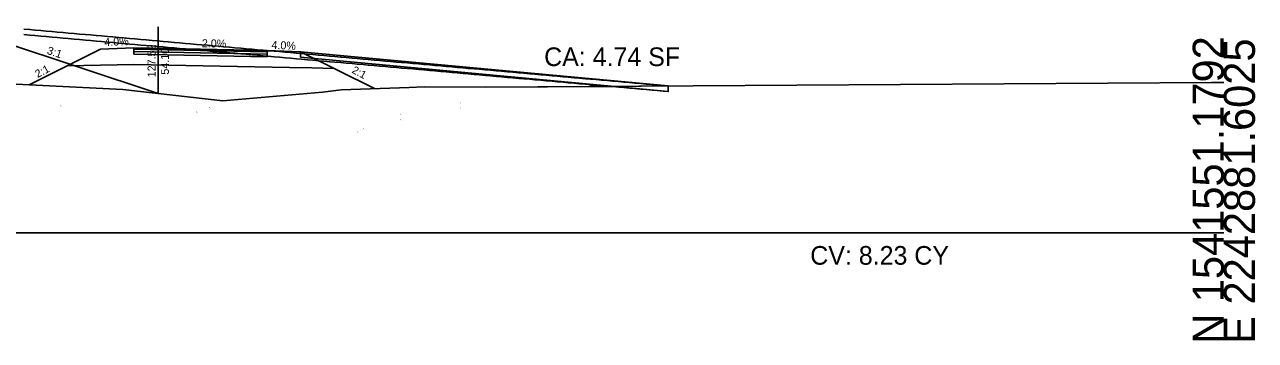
# Model space of a CAD drawing. Extents: x -26 to 1303, y -13 to 9563.
# Drawn here: x 192.1 to 302.8, y 4990.3 to 5018.7 of the extents above; entities that cross this region are included whole.
import ezdxf

# ---------------------------------------------------------------- set-up
doc = ezdxf.new("R2010")
doc.units = 0
for name, color, linetype in [('ASPHALT_19MM1', 7, 'Continuous'), ('ASPHALT_9_5MM1', 7, 'Continuous'), ('Default', 7, 'Continuous'), ('DTM_P_FINISHED_GRADE', 7, 'Continuous'), ('DTM_X_GROUND', 7, 'Continuous'), ('XS_CELL', 7, 'Continuous'), ('XS_M_SHAPES_EARTHWORK', 7, 'Continuous'), ('XS_P_DR_GRAVEL', 7, 'Continuous'), ('XS_P_GROUND', 7, 'Continuous'), ('XS_P_SHOULDER', 7, 'Continuous'), ('XS_P_SUBGRADE_GRANULAR', 7, 'Continuous'), ('XS_P_TX_CLEARZONE', 7, 'Continuous'), ('XS_P_TX_FS_BS', 7, 'Continuous'), ('XS_SHEET_EW_TX_AREA', 7, 'Continuous'), ('XS_SHEET_EW_TX_VOLUME', 7, 'Continuous')]:
    doc.layers.add(name, color=color, linetype=linetype)

msp = doc.modelspace()

# ---------------------------------------------------------------- linework, layer by layer
at = {"layer": 'ASPHALT_19MM1'}
for p, q in [((201.91, 5016.32), (213.91, 5016.08)), ((201.91, 5016.07), (201.91, 5016.32)), ((201.91, 5016.07), (213.91, 5015.83)), ((213.91, 5015.83), (213.91, 5016.08))]:
    msp.add_line(p, q, dxfattribs=at)
at = {"layer": 'ASPHALT_9_5MM1'}
for p, q in [((201.91, 5016.65), (213.91, 5016.41)), ((201.91, 5016.32), (201.91, 5016.65)), ((201.91, 5016.53), (213.91, 5016.29)), ((213.91, 5016.08), (213.91, 5016.41))]:
    msp.add_line(p, q, dxfattribs=at)
at = {"layer": 'DTM_P_FINISHED_GRADE'}
msp.add_lwpolyline([(192, 5018.33), (192.54, 5018.28), (193, 5018.24), (193.54, 5018.19), (194, 5018.15), (194.54, 5018.1), (195, 5018.06), (195.54, 5018.01), (196, 5017.97), (196.54, 5017.92), (197, 5017.88), (197.54, 5017.84), (198, 5017.8), (198.54, 5017.75), (199, 5017.71), (199.54, 5017.66), (200, 5017.62), (200.54, 5017.57), (201, 5017.53), (201.54, 5017.48), (202, 5017.44), (202.54, 5017.39), (203, 5017.35), (203.54, 5017.31), (204, 5017.27), (204.54, 5017.22), (205, 5017.18), (205.54, 5017.13), (206, 5017.09), (206.54, 5017.04), (207, 5017), (207.54, 5016.95), (208, 5016.91), (208.54, 5016.87), (209, 5016.82), (209.54, 5016.78), (210, 5016.74), (210.54, 5016.69), (211, 5016.65), (211.54, 5016.6), (212, 5016.56), (212.54, 5016.51), (213, 5016.47), (213.54, 5016.42), (214, 5016.38), (214.54, 5016.34), (215, 5016.3), (215.54, 5016.25), (216, 5016.21), (216.54, 5016.16), (217, 5016.12), (217.54, 5016.07), (218, 5016.03), (218.54, 5015.98), (219, 5015.94), (219.54, 5015.89), (220, 5015.85), (220.54, 5015.81), (221, 5015.77), (221.54, 5015.72), (222, 5015.68), (222.54, 5015.63), (223, 5015.59), (223.54, 5015.54), (224, 5015.5), (224.54, 5015.45), (225, 5015.41), (225.54, 5015.36), (226, 5015.32), (226.54, 5015.28), (227, 5015.24), (227.54, 5015.19), (228, 5015.15), (228.54, 5015.1), (229, 5015.06), (229.54, 5015.01), (230, 5014.97), (230.54, 5014.92), (231, 5014.88), (231.54, 5014.83), (232, 5014.79), (232.54, 5014.75), (233, 5014.71), (233.54, 5014.66), (234, 5014.62), (234.54, 5014.57), (235, 5014.53), (235.54, 5014.48), (236, 5014.44), (236.54, 5014.39), (237, 5014.35), (237.54, 5014.31), (238, 5014.26), (238.54, 5014.22), (239, 5014.18), (239.54, 5014.13), (240, 5014.09), (240.54, 5014.04), (241, 5014), (241.54, 5013.95), (242, 5013.91), (242.54, 5013.86), (243, 5013.82), (243.54, 5013.78), (244, 5013.74), (244.54, 5013.69), (245, 5013.65), (245.54, 5013.6), (246, 5013.56), (246.54, 5013.51), (247, 5013.47), (247.54, 5013.42), (248, 5013.38), (248.54, 5013.33), (249, 5013.29), (249.54, 5013.25), (250, 5013.21)], dxfattribs=at)
at = {"layer": 'DTM_X_GROUND'}
msp.add_lwpolyline([(190.7, 5013.41), (200.92, 5012.88), (209.91, 5011.87), (218.88, 5012.65), (220.55, 5012.87), (226.67, 5013.07), (228.04, 5013.13), (233.58, 5013.1), (298.88, 5013.52), (300, 5013.51)], dxfattribs=at)
at = {"layer": 'XS_CELL'}
msp.add_line((150, 5000), (300, 5000), dxfattribs=at)
at = {"layer": 'XS_M_SHAPES_EARTHWORK'}
msp.add_lwpolyline([(190.7, 5013.41), (200.92, 5012.88), (209.91, 5011.87), (218.88, 5012.65), (220.55, 5012.87), (226.67, 5013.07), (228.04, 5013.13), (233.58, 5013.1), (244.72, 5013.17), (244.54, 5013.19), (244, 5013.24), (243.54, 5013.28), (243, 5013.32), (242.54, 5013.36), (242, 5013.41), (241.54, 5013.45), (241, 5013.5), (240.54, 5013.54), (240, 5013.59), (239.54, 5013.63), (239, 5013.68), (238.54, 5013.72), (238, 5013.76), (237.54, 5013.81), (237, 5013.85), (236.54, 5013.89), (236, 5013.94), (235.54, 5013.98), (235, 5014.03), (234.54, 5014.07), (234, 5014.12), (233.54, 5014.16), (233, 5014.21), (232.54, 5014.25), (232, 5014.29), (231.54, 5014.33), (231, 5014.38), (230.54, 5014.42), (230, 5014.47), (229.54, 5014.51), (229, 5014.56), (228.54, 5014.6), (228, 5014.65), (227.54, 5014.69), (227, 5014.74), (226.54, 5014.78), (226, 5014.82), (225.54, 5014.86), (225, 5014.91), (224.54, 5014.95), (224, 5015), (223.54, 5015.04), (223, 5015.09), (222.54, 5015.13), (222, 5015.18), (221.54, 5015.22), (221, 5015.27), (220.54, 5015.31), (220, 5015.35), (219.54, 5015.39), (219, 5015.44), (218.54, 5015.48), (218, 5015.53), (217.54, 5015.57), (217, 5015.62), (216.54, 5015.66), (216, 5015.71), (215.54, 5015.75), (215, 5015.8), (214.54, 5015.84), (214, 5015.88), (213.54, 5015.92), (213, 5015.97), (212.54, 5016.01), (212, 5016.06), (211.54, 5016.1), (211, 5016.15), (210.54, 5016.19), (210, 5016.24), (209.54, 5016.28), (209, 5016.32), (208.54, 5016.37), (208, 5016.41), (207.54, 5016.45), (207, 5016.5), (206.54, 5016.54), (206, 5016.59), (205.54, 5016.63), (205, 5016.68), (204.54, 5016.72), (204, 5016.77), (203.54, 5016.81), (203, 5016.85), (202.54, 5016.89), (202, 5016.94), (201.54, 5016.98), (201, 5017.03), (200.54, 5017.07), (200, 5017.12), (199.54, 5017.16), (199, 5017.21), (198.54, 5017.25), (198, 5017.3), (197.54, 5017.34), (197, 5017.38), (196.54, 5017.42), (196, 5017.47), (195.54, 5017.51), (195, 5017.56), (194.54, 5017.6), (194, 5017.65), (193.54, 5017.69), (193, 5017.74), (192.54, 5017.78), (192, 5017.83)], dxfattribs=at)
msp.add_lwpolyline([(244.72, 5013.17), (250, 5013.21), (250, 5012.71), (249.54, 5012.75), (249, 5012.79), (248.54, 5012.83), (248, 5012.88), (247.54, 5012.92), (247, 5012.97), (246.54, 5013.01), (246, 5013.06), (245.54, 5013.1), (245, 5013.15)], close=True, dxfattribs=at)
at = {"layer": 'XS_P_DR_GRAVEL'}
for p, q in [((216.91, 5016.29), (250, 5013.21)), ((216.91, 5016.29), (216.91, 5015.79)), ((216.91, 5015.79), (250, 5012.71))]:
    msp.add_line(p, q, dxfattribs=at)
msp.add_lwpolyline([(192, 5017.83), (192.54, 5017.78), (193, 5017.74), (193, 5017.74), (193.54, 5017.69), (194, 5017.65), (194, 5017.65), (194.54, 5017.6), (194.54, 5017.6), (195, 5017.56), (195.54, 5017.51), (195.54, 5017.51), (196, 5017.47), (196.54, 5017.42), (196.54, 5017.42), (197, 5017.38), (197.54, 5017.34), (197.54, 5017.34), (198, 5017.3), (198.54, 5017.25), (198.54, 5017.25), (199, 5017.21), (199.54, 5017.16), (199.54, 5017.16), (200, 5017.12), (200.54, 5017.07), (200.54, 5017.07), (201, 5017.03), (201.54, 5016.98), (201.54, 5016.98), (202, 5016.94), (202.54, 5016.89), (202.54, 5016.89), (203, 5016.85), (203.54, 5016.81), (203.54, 5016.81), (204, 5016.77), (204.54, 5016.72), (204.54, 5016.72), (205, 5016.68), (205.54, 5016.63), (205.54, 5016.63), (206, 5016.59), (206.54, 5016.54), (206.54, 5016.54), (207, 5016.5), (207.54, 5016.45), (207.54, 5016.45), (208, 5016.41), (208.54, 5016.37), (208.54, 5016.37), (209, 5016.32), (209.54, 5016.28), (209.54, 5016.28), (210, 5016.24), (210.54, 5016.19), (210.54, 5016.19), (211, 5016.15), (211.54, 5016.1), (211.54, 5016.1), (212, 5016.06), (212.54, 5016.01), (212.54, 5016.01), (213, 5015.97), (213.54, 5015.92), (213.54, 5015.92), (214, 5015.88), (214.54, 5015.84), (214.54, 5015.84), (215, 5015.8), (215.54, 5015.75), (215.54, 5015.75), (216, 5015.71), (216.54, 5015.66), (216.54, 5015.66), (217, 5015.62), (217.54, 5015.57), (217.54, 5015.57), (218, 5015.53), (218.54, 5015.48), (218.54, 5015.48), (219, 5015.44), (219.54, 5015.39), (219.54, 5015.39), (220, 5015.35), (220.54, 5015.31), (220.54, 5015.31), (221, 5015.27), (221.54, 5015.22), (221.54, 5015.22), (222, 5015.18), (222.54, 5015.13), (222.54, 5015.13), (223, 5015.09), (223.54, 5015.04), (223.54, 5015.04), (224, 5015), (224.54, 5014.95), (224.54, 5014.95), (225, 5014.91), (225.54, 5014.86), (225.54, 5014.86), (226, 5014.82), (226.54, 5014.78), (226.54, 5014.78), (227, 5014.74), (227.54, 5014.69), (227.54, 5014.69), (228, 5014.65), (228.54, 5014.6), (228.54, 5014.6), (229, 5014.56), (229.54, 5014.51), (229.54, 5014.51), (230, 5014.47), (230.54, 5014.42), (230.54, 5014.42), (231, 5014.38), (231.54, 5014.33), (231.54, 5014.33), (232, 5014.29), (232.54, 5014.25), (232.54, 5014.25), (233, 5014.21), (233.54, 5014.16), (233.54, 5014.16), (234, 5014.12), (234.54, 5014.07), (234.54, 5014.07), (235, 5014.03), (235.54, 5013.98), (235.54, 5013.98), (236, 5013.94), (236.54, 5013.89), (236.54, 5013.89), (237, 5013.85), (237.54, 5013.81), (237.54, 5013.81), (238, 5013.76), (238.54, 5013.72), (238.54, 5013.72), (239, 5013.68), (239.54, 5013.63), (239.54, 5013.63), (240, 5013.59), (240.54, 5013.54), (240.54, 5013.54), (241, 5013.5), (241.54, 5013.45), (241.54, 5013.45), (242, 5013.41), (242.54, 5013.36), (242.54, 5013.36), (243, 5013.32), (243.54, 5013.28), (243.54, 5013.28), (244, 5013.24), (244.54, 5013.19), (244.54, 5013.19), (245, 5013.15), (245.54, 5013.1), (245.54, 5013.1), (246, 5013.06), (246.54, 5013.01), (246.54, 5013.01), (247, 5012.97), (247.54, 5012.92), (247.54, 5012.92), (248, 5012.88), (248.54, 5012.83), (248.54, 5012.83), (249, 5012.79), (249.54, 5012.75), (249.54, 5012.75), (250, 5012.71), (250, 5013.21), (249.54, 5013.25), (249.54, 5013.25), (249, 5013.29), (248.54, 5013.33), (248.54, 5013.33), (248, 5013.38), (247.54, 5013.42), (247.54, 5013.42), (247, 5013.47), (246.54, 5013.51), (246.54, 5013.51), (246, 5013.56), (245.54, 5013.6), (245.54, 5013.6), (245, 5013.65), (244.54, 5013.69), (244.54, 5013.69), (244, 5013.74), (243.54, 5013.78), (243.54, 5013.78), (243, 5013.82), (242.54, 5013.86), (242.54, 5013.86), (242, 5013.91), (241.54, 5013.95), (241.54, 5013.95), (241, 5014), (240.54, 5014.04), (240.54, 5014.04), (240, 5014.09), (239.54, 5014.13), (239.54, 5014.13), (239, 5014.18), (238.54, 5014.22), (238.54, 5014.22), (238, 5014.26), (237.54, 5014.31), (237.54, 5014.31), (237, 5014.35), (236.54, 5014.39), (236.54, 5014.39), (236, 5014.44), (235.54, 5014.48), (235.54, 5014.48), (235, 5014.53), (234.54, 5014.57), (234.54, 5014.57), (234, 5014.62), (233.54, 5014.66), (233.54, 5014.66), (233, 5014.71), (232.54, 5014.75), (232.54, 5014.75), (232, 5014.79), (231.54, 5014.83), (231.54, 5014.83), (231, 5014.88), (230.54, 5014.92), (230.54, 5014.92), (230, 5014.97), (229.54, 5015.01), (229.54, 5015.01), (229, 5015.06), (228.54, 5015.1), (228.54, 5015.1), (228, 5015.15), (227.54, 5015.19), (227.54, 5015.19), (227, 5015.24), (226.54, 5015.28), (226.54, 5015.28), (226, 5015.32), (225.54, 5015.36), (225.54, 5015.36), (225, 5015.41), (224.54, 5015.45), (224.54, 5015.45), (224, 5015.5), (223.54, 5015.54), (223.54, 5015.54), (223, 5015.59), (222.54, 5015.63), (222.54, 5015.63), (222, 5015.68), (221.54, 5015.72), (221.54, 5015.72), (221, 5015.77), (220.54, 5015.81), (220.54, 5015.81), (220, 5015.85), (219.54, 5015.89), (219.54, 5015.89), (219, 5015.94), (218.54, 5015.98), (218.54, 5015.98), (218, 5016.03), (217.54, 5016.07), (217.54, 5016.07), (217, 5016.12), (216.54, 5016.16), (216.54, 5016.16), (216, 5016.21), (215.54, 5016.25), (215.54, 5016.25), (215, 5016.3), (214.54, 5016.34), (214.54, 5016.34), (214, 5016.38), (213.54, 5016.42), (213.54, 5016.42), (213, 5016.47), (212.54, 5016.51), (212.54, 5016.51), (212, 5016.56), (211.54, 5016.6), (211.54, 5016.6), (211, 5016.65), (210.54, 5016.69), (210.54, 5016.69), (210, 5016.74), (209.54, 5016.78), (209.54, 5016.78), (209, 5016.82), (208.54, 5016.87), (208.54, 5016.87), (208, 5016.91), (207.54, 5016.95), (207.54, 5016.95), (207, 5017), (206.54, 5017.04), (206.54, 5017.04), (206, 5017.09), (205.54, 5017.13), (205.54, 5017.13), (205, 5017.18), (204.54, 5017.22), (204.54, 5017.22), (204, 5017.27), (203.54, 5017.31), (203.54, 5017.31), (203, 5017.35), (202.54, 5017.39), (202.54, 5017.39), (202, 5017.44), (201.54, 5017.48), (201.54, 5017.48), (201, 5017.53), (200.54, 5017.57), (200.54, 5017.57), (200, 5017.62), (199.54, 5017.66), (199.54, 5017.66), (199, 5017.71), (198.54, 5017.75), (198.54, 5017.75), (198, 5017.8), (197.54, 5017.84), (197.54, 5017.84), (197, 5017.88), (196.54, 5017.92), (196.54, 5017.92), (196, 5017.97), (195.54, 5018.01), (195.54, 5018.01), (195, 5018.06), (194.54, 5018.1), (194.54, 5018.1), (194, 5018.15), (194, 5018.15), (193.54, 5018.19), (193, 5018.24), (193, 5018.24), (192.54, 5018.28), (192, 5018.33)], dxfattribs=at)
at = {"layer": 'XS_P_GROUND'}
msp.add_lwpolyline([(180.92, 5018.73), (190, 5017.22), (204.1, 5012.52)], dxfattribs=at)
at = {"layer": 'XS_P_SHOULDER'}
for p, q in [((198.91, 5016.53), (192.47, 5013.31)), ((223.56, 5012.97), (216.91, 5016.29))]:
    msp.add_line(p, q, dxfattribs=at)
for points in [[(198.91, 5016.53), (201.91, 5016.65)], [(213.91, 5016.41), (216.91, 5016.29)]]:
    msp.add_lwpolyline(points, dxfattribs=at)
at = {"layer": 'XS_P_SUBGRADE_GRANULAR'}
for points in [[(201.91, 5015.15), (195.91, 5015.03)], [(201.91, 5015.15), (215.91, 5014.87)], [(215.91, 5014.87), (217.91, 5014.83), (219.91, 5014.79)]]:
    msp.add_lwpolyline(points, dxfattribs=at)
at = {"layer": 'XS_P_TX_CLEARZONE'}
msp.add_line((204.1, 5012.52), (204.1, 5018.52), dxfattribs=at)
msp.add_line((204.1, 5012.52), (204.1, 5018.52), dxfattribs=at)
msp.add_line((204.1, 5012.52), (204.1, 5018.52), dxfattribs=at)

# ---------------------------------------------------------------- texts
at = {"layer": 'Default'}
for p in [(204.06, 5012.46), (204.06, 5012.46), (195.26, 5011.39), (195.26, 5011.39), (208.68, 5011.2), (231.25, 5011.63), (231.25, 5011.15), (207.51, 5010.81), (225.87, 5010.61), (225.87, 5010.13), (222, 5009.02), (222.54, 5009.32)]:
    msp.add_text('X', height=0.12, dxfattribs=at).set_placement(p)
at = {"layer": 'XS_CELL'}
for s, p in [('N 1541551.1792', (300, 4990)), ('E 2242881.6025', (302.8, 4990))]:
    msp.add_text(s, height=2.8, rotation=90, dxfattribs=at).set_placement(p)
at = {"layer": 'XS_P_TX_CLEARZONE'}
for s, p in [('127.52', (203.86, 5013.99)), ('127.52', (203.86, 5013.99)), ('127.52', (203.86, 5013.99)), ("54.10'", (205.06, 5014.23)), ("54.10'", (205.06, 5014.23)), ("54.10'", (205.06, 5014.23))]:
    msp.add_text(s, height=0.72, rotation=90, dxfattribs=at).set_placement(p)
at = {"layer": 'XS_P_TX_FS_BS'}
for s, height, rotation, p in [('3:1', 0.72, 341.5668, (194.03, 5016.11)), ('4.0%', 0.72, 2.2906, (199.26, 5016.8)), ('2.0%', 0.72, 358.8542, (208.02, 5016.7)), ('4.0%', 0.72, 357.7094, (214.28, 5016.55)), ('2:1', 0.7, 27.7837, (193.24, 5013.92)), ('2:1', 0.7, 332.2163, (221.46, 5014.43))]:
    msp.add_text(s, height=height, rotation=rotation, dxfattribs=at).set_placement(p)
at = {"layer": 'XS_SHEET_EW_TX_AREA'}
msp.add_text('CA: 4.74 SF', height=1.68, dxfattribs=at).set_placement((238.83, 5015))
at = {"layer": 'XS_SHEET_EW_TX_VOLUME'}
msp.add_text('CV: 8.23 CY', height=1.68, dxfattribs=at).set_placement((262.78, 4997.12))

doc.saveas('drawing.dxf')
